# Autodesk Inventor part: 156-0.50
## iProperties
Created: 2007-07
Part Number: 156-0.50
Document SubType Name: Modeling
Designer: btaylor
Density: 1 g/cm^3
Author: btaylor
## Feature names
1. Loft1
2. Loft2
3. Extrusion2
4. Extrusion4
5. Extrusion5
6. Fillet1
7. Fillet2
8. Chamfer1
9. Fillet3
10. Chamfer2
11. Fillet4
12. Fillet5
